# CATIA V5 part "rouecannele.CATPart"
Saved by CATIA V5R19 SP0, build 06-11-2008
Part number: Rouecannele
Publications: "Axe", "Appui_1", "Appui_2"
Bounding box of the stored display mesh (mm): x 0 to 23, y -75.702 to 75.705, z -75.7 to 75.704
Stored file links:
  C:\Users\Martin\Documents\IFMA\Cfao\Projet S3\rouecannele.CATPart
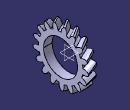
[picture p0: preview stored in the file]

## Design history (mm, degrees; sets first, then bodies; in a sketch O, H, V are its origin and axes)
Parameters
  diametre_primitif = 137.4094 mm {= module_app *z_dent}
  diametre_tete = 151.4094 mm {= diametre_primitif +2*module_normal}
  diametre_pied = 119.9094 mm {= diametre_primitif -2*1.25*module_normal}
  diametre_base = 129.1226 mm {= diametre_primitif *cos(angle_pression )}
  module_normal = 7 mm
  module_app = 8.0829 mm {= module_normal /cos(angle_helice )}
  angle_pression = 20 deg
  angle_helice = 30 deg
  z_dent = 17
  diametre_alesage = 77.9094 mm {= diametre_pied -6*module_normal}
  largeur_denture = 23 mm
  pas_helice = 747.6991 mm {= PI *diametre_primitif /tan(angle_helice )}
Set1
  Point1: (0, 0, 0)
  Line1: type PtDir, Direction yz-plane, Start 0, End 20, RefPoint Point1
  Point2: (-5, 0, 68.7047 {= diametre_primitif /2})
  Helix1: Pitch 747.6991 {= pas_helice}, TaperAngle 0, Height 33 {= largeur_denture +10mm}, Direction Line1, RefPoint Point2
  Line2: type PtDir, Direction xy-plane, Start 0, End 20, RefPoint Point1
  Plane1: type Normal, Curve Helix1, RefPoint Point2
Body1 (main body)
  Sketch1 on yz-plane, origin (0, 0, 0), H (0, 1, 0), V (0, 0, 1)
    circle A1 centre (0, 0) radius 59.9547
    circle A2 centre (0, 0) radius 38.9547
    radius A2 = 38.9547 {= diametre_alesage /2}
    radius A1 = 59.9547 {= diametre_pied /2}
  Pad1: profile Sketch1, direction (1, 0, 0), length 23 {= largeur_denture}
  Sketch2 on Plane1, origin (-6.8068, 3.1295, 0), H (-0.5, 0.866, 0), V (0, 0, 1)
    construction circle A1 centre (-3.6136, 0) radius 68.7047
    reference intersected point E1 (-3.6136, 0) from axis of face of Pad1
    reference projected point E2 (-3.6136, 68.7047) from Point2
    construction circle A2 centre (-3.6136, 0) radius 64.5613
    construction line L1 (-3.6136, 68.7047) -> (-3.6136, 0)
    point P2 (-3.6136, 68.7047)
    construction line L2 (-3.6136, 0) -> (-25.6949, 60.6678)
    point P3 (-25.6949, 60.6678)
    arc A3 centre (-25.6949, 60.6678) radius 23.4984 from (-7.3055, 46.0388) to (-9.8718, 78.0403) ccw
    point P4 (-3.6136, 68.7047)
    construction line L3 (-3.6136, 0) -> (-9.1055, 68.4848)
    point P5 (-3.6136, 0)
    point P6 (-9.1055, 68.4848)
    arc A4 centre (8.5175, 63.4113) radius 23.4984 from (-7.3055, 46.0388) to (-9.8718, 78.0403) cw
    radius A2 = 64.5613 {= diametre_base /2}
    angle L2 L1 = 20 {= angle_pression}
    angle L3 L1 = 4.5848 {= PI *module_normal /4/(diametre_primitif /2)*1rad}
    concentricity: E1 A1
    coincidence: A1 E2, P2 A1, P3 A2, A3 P4, P4 L1, A3 P2, P5 H, P5 L2, P6 A1
    vertical: L1 V
    symmetry: A4 A3 L3
  Rib1: profile Sketch2, centre curve Helix1
  CircPattern1: of Rib1, instances 17 {= z_dent}, angular step 21.1765 {= 360.0*1 deg/CircPattern1.AngularNumber}, axis from face
  Split1: SplitPlane face
  Split2: SplitPlane face
  Sketch3 on yz-plane, origin (0, 0, 0), H (0, 1, 0), V (0, 0, 1)
    circle A1 centre (0, 0) radius 75.7047
    radius A1 = 75.7047 {= diametre_tete /2}
  Pocket1: profile Sketch3, direction (1, 0, 0), through (limit type 6), outer side
  Sketch4 on yz-plane, origin (0, 0, 0), H (0, 1, 0), V (0, 0, 1)
    circle A1 centre (0, 0) radius 45.9547
    radius A1 = 45.9547 {= diametre_pied/2 -2*module_normal}
  Pocket2: profile Sketch4, direction (1, 0, 0), through (limit type 6)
